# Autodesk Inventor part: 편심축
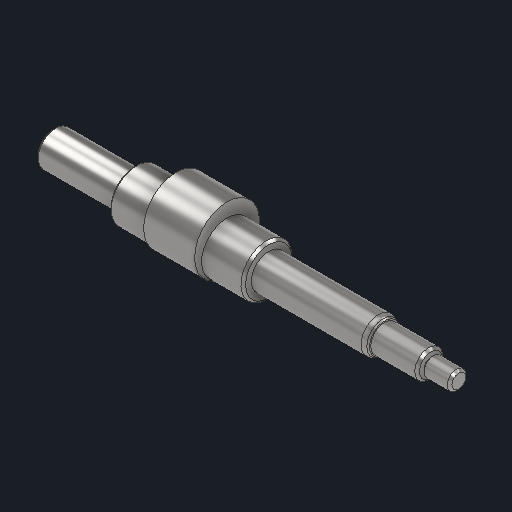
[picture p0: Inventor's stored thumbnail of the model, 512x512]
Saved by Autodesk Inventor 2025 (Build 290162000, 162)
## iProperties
Created: 2025-08
Part Number: 편심축
Material: 강철, 연강
Document SubType Name: Modeling
Designer: infra005
Density: 7.86 g/cm^3
Appearance: 기본값
Author: jhkim
Sending System: Autodesk Inventor 2026
Preprocessor: ST-DEVELOPER v20.1
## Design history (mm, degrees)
feature "솔리드1"
node "솔리드2"
